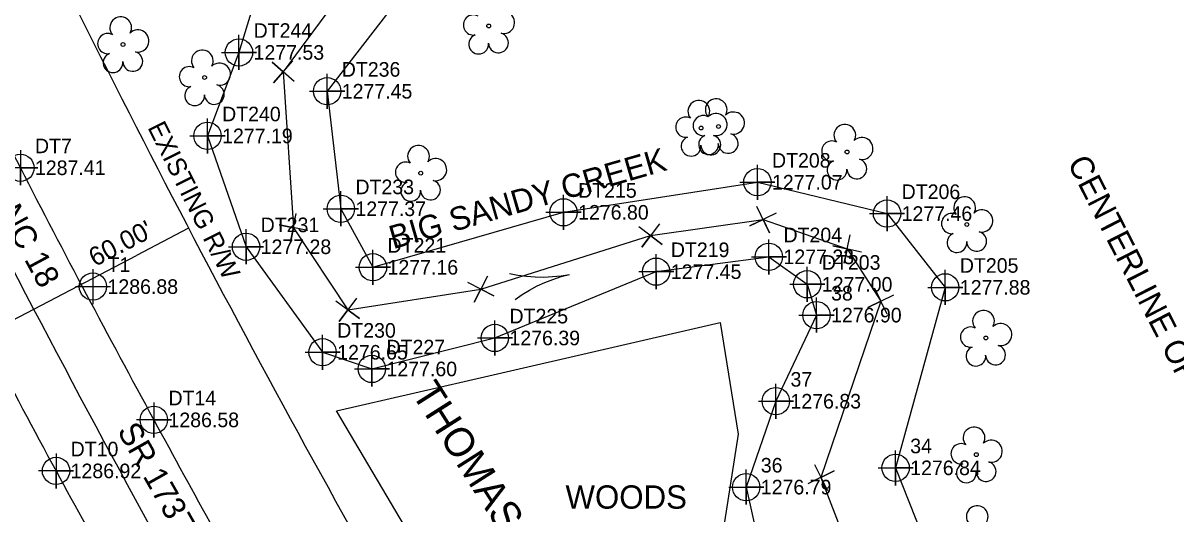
# Model space of a CAD drawing. Extents: x 1393723 to 1394549, y 957573 to 958412.
# Drawn here: x 1394117.7 to 1394315.1, y 958218.3 to 958302.5 of the extents above; entities that cross this region are included whole.
import ezdxf

# ---------------------------------------------------------------- set-up
doc = ezdxf.new("R2010")
doc.units = 0
for name, color, linetype in [('Cogo Default Point CELL', 7, 'Continuous'), ('COGO Default Point Elevation', 7, 'Continuous'), ('COGO Default Point Number', 7, 'Continuous'), ('Exist Horizontal Alignment', 7, 'Continuous'), ('Exist Hydro Jurisdictional Stream or Body of Water', 7, 'Continuous'), ('Exist Hydro Jurisdictional Stream or Body of Water Text', 7, 'Continuous'), ('Exist Hydro Stream Flow Arrow CELL', 7, 'Continuous'), ('Exist Hydro Stream or Body of Water Cogo Elevation', 7, 'Continuous'), ('Exist Hydro Stream or Body of Water Cogo Number', 7, 'Continuous'), ('Exist Hydro Stream or Body of Water Cogo Point CELL', 7, 'Continuous'), ('Exist Property Corner CELL', 7, 'Continuous'), ('Exist Property Line', 7, 'Continuous'), ('Exist Property Line Text', 7, 'Continuous'), ('Exist Property Owner Text', 7, 'Continuous'), ('Exist Right of Way Line', 7, 'Continuous'), ('Exist Right of Way Line Text', 7, 'Continuous'), ('Exist Right of Way Width CELL', 7, 'Continuous'), ('Exist Roads EOP', 7, 'Continuous'), ('Exist Roads EOP Cogo Elevation', 7, 'Continuous'), ('Exist Roads EOP Cogo Number', 7, 'Continuous'), ('Exist Roads EOP Cogo Point CELL', 7, 'Continuous'), ('Exist Roads EOP Text', 7, 'Continuous'), ('Exist Vegetation Tree CELL', 7, 'Continuous'), ('Exist Vegetation Woods Line', 7, 'Continuous'), ('Exist Vegetation Woods Line Text', 7, 'Continuous')]:
    doc.layers.add(name, color=color, linetype=linetype)

msp = doc.modelspace()

# ---------------------------------------------------------------- linework, layer by layer
at = {"layer": 'Cogo Default Point CELL'}
for points in [[(1394129.65, 958260.32), (1394129.65, 958257.32)], [(1394126.65, 958257.32), (1394129.65, 958257.32)], [(1394129.65, 958257.32), (1394132.65, 958257.32)], [(1394129.65, 958257.32), (1394129.65, 958254.32)]]:
    msp.add_lwpolyline(points, dxfattribs=at)
msp.add_circle((1394129.65, 958257.32), 2.34, dxfattribs=at)
at = {"layer": 'Exist Horizontal Alignment'}
msp.add_arc((1396149.77, 959316.7), 2291.83, 206.42564, 210.98819, dxfattribs=at)
at = {"layer": 'Exist Hydro Jurisdictional Stream or Body of Water'}
for points in [[(1394173.56, 958323.84), (1394160.39, 958316.41), (1394154.66, 958297.46), (1394149.27, 958283.15), (1394155.87, 958264.15), (1394168.98, 958246.06), (1394177.42, 958243.2), (1394198.48, 958248.51), (1394226.11, 958259.88), (1394245.4, 958262.42), (1394251.97, 958257.71), (1394253.55, 958252.43), (1394246.6, 958237.67), (1394241.52, 958222.95), (1394245.4, 958205.43), (1394258.52, 958177.52), (1394261.1, 958155.62), (1394254.7, 958129.06), (1394238.9, 958116.03), (1394219.59, 958103.52)], [(1394182.65, 958307.54), (1394169.76, 958290.8), (1394172.1, 958270.66), (1394177.6, 958260.63), (1394210.23, 958270.05), (1394243.43, 958275.21), (1394265.63, 958269.83), (1394275.6, 958257.19), (1394267.1, 958226.25), (1394278.61, 958197.12), (1394277.84, 958154), (1394270.52, 958123.51), (1394228.57, 958088.78)]]:
    msp.add_lwpolyline(points, dxfattribs=at)
at = {"layer": 'Exist Hydro Stream Flow Arrow CELL'}
msp.add_line((1394206.36, 958258.37), (1394206.36, 958258.37), dxfattribs=at)
for points in [[(1394200.99, 958259.57), (1394202.43, 958259.26), (1394203.92, 958259.1), (1394205.39, 958258.97), (1394206.84, 958258.96), (1394208.32, 958259.03), (1394209.81, 958259.18), (1394211.25, 958259.41)], [(1394201.94, 958255.09), (1394203.13, 958255.96), (1394204.43, 958256.71), (1394205.72, 958257.43), (1394207.03, 958258.03), (1394208.42, 958258.56), (1394209.84, 958259.03), (1394211.25, 958259.41)]]:
    msp.add_lwpolyline(points, dxfattribs=at)
at = {"layer": 'Exist Hydro Stream or Body of Water Cogo Point CELL'}
for points in [[(1394151.66, 958297.46), (1394157.66, 958297.46), (1394154.66, 958297.46), (1394154.66, 958294.46), (1394154.66, 958300.46)], [(1394166.76, 958290.8), (1394172.76, 958290.8), (1394169.76, 958290.8), (1394169.76, 958287.8), (1394169.76, 958293.8)], [(1394146.27, 958283.15), (1394152.27, 958283.15), (1394149.27, 958283.15), (1394149.27, 958280.15), (1394149.27, 958286.15)], [(1394240.43, 958275.21), (1394246.43, 958275.21), (1394243.43, 958275.21), (1394243.43, 958272.21), (1394243.43, 958278.21)], [(1394169.1, 958270.66), (1394175.1, 958270.66), (1394172.1, 958270.66), (1394172.1, 958267.66), (1394172.1, 958273.66)], [(1394207.23, 958270.05), (1394213.23, 958270.05), (1394210.23, 958270.05), (1394210.23, 958267.05), (1394210.23, 958273.05)], [(1394262.63, 958269.83), (1394268.63, 958269.83), (1394265.63, 958269.83), (1394265.63, 958266.83), (1394265.63, 958272.83)], [(1394152.87, 958264.15), (1394158.87, 958264.15), (1394155.87, 958264.15), (1394155.87, 958261.15), (1394155.87, 958267.15)], [(1394242.4, 958262.42), (1394248.4, 958262.42), (1394245.4, 958262.42), (1394245.4, 958259.42), (1394245.4, 958265.42)], [(1394174.6, 958260.63), (1394180.6, 958260.63), (1394177.6, 958260.63), (1394177.6, 958257.63), (1394177.6, 958263.63)], [(1394223.11, 958259.88), (1394229.11, 958259.88), (1394226.11, 958259.88), (1394226.11, 958256.88), (1394226.11, 958262.88)], [(1394248.97, 958257.71), (1394254.97, 958257.71), (1394251.97, 958257.71), (1394251.97, 958254.71), (1394251.97, 958260.71)], [(1394272.6, 958257.19), (1394278.6, 958257.19), (1394275.6, 958257.19), (1394275.6, 958254.19), (1394275.6, 958260.19)], [(1394250.55, 958252.43), (1394256.55, 958252.43), (1394253.55, 958252.43), (1394253.55, 958249.43), (1394253.55, 958255.43)], [(1394195.48, 958248.51), (1394201.48, 958248.51), (1394198.48, 958248.51), (1394198.48, 958245.51), (1394198.48, 958251.51)], [(1394165.98, 958246.06), (1394171.98, 958246.06), (1394168.98, 958246.06), (1394168.98, 958243.06), (1394168.98, 958249.06)], [(1394174.42, 958243.2), (1394180.42, 958243.2), (1394177.42, 958243.2), (1394177.42, 958240.2), (1394177.42, 958246.2)], [(1394243.6, 958237.67), (1394249.6, 958237.67), (1394246.6, 958237.67), (1394246.6, 958234.67), (1394246.6, 958240.67)], [(1394264.1, 958226.25), (1394270.1, 958226.25), (1394267.1, 958226.25), (1394267.1, 958223.25), (1394267.1, 958229.25)], [(1394238.52, 958222.95), (1394244.52, 958222.95), (1394241.52, 958222.95), (1394241.52, 958219.95), (1394241.52, 958225.95)]]:
    msp.add_lwpolyline(points, dxfattribs=at)
for centre in [(1394154.66, 958297.46), (1394169.76, 958290.8), (1394149.27, 958283.15), (1394243.43, 958275.21), (1394172.1, 958270.66), (1394210.23, 958270.05), (1394265.63, 958269.83), (1394155.87, 958264.15), (1394177.6, 958260.63), (1394245.4, 958262.42), (1394226.11, 958259.88), (1394251.97, 958257.71), (1394275.6, 958257.19), (1394253.55, 958252.43), (1394198.48, 958248.51), (1394168.98, 958246.06), (1394177.42, 958243.2), (1394246.6, 958237.67), (1394267.1, 958226.25), (1394241.52, 958222.95)]:
    msp.add_circle(centre, 2.34, dxfattribs=at)
at = {"layer": 'Exist Property Corner CELL'}
for p, q in [((1394162.21, 958294.13), (1394162.21, 958294.13)), ((1394244.41, 958268.82), (1394244.41, 958268.82)), ((1394163.98, 958267.41), (1394163.98, 958267.41)), ((1394225.15, 958266.05), (1394225.15, 958266.05)), ((1394258.8, 958263.77), (1394258.8, 958263.77)), ((1394196.06, 958256.89), (1394196.06, 958256.89)), ((1394173.29, 958253.34), (1394173.29, 958253.34)), ((1394264.57, 958254.81), (1394264.57, 958254.81)), ((1394254.31, 958224.6), (1394254.31, 958224.6))]:
    msp.add_line(p, q, dxfattribs=at)
for points in [[(1394164.09, 958292.48), (1394160.33, 958295.77), (1394162.21, 958294.13), (1394160.56, 958292.24), (1394163.86, 958296.01)], [(1394246.67, 958269.9), (1394242.16, 958267.73), (1394244.41, 958268.82), (1394245.5, 958266.56), (1394243.33, 958271.07)], [(1394166.43, 958266.91), (1394161.54, 958267.91), (1394163.98, 958267.41), (1394163.49, 958264.96), (1394164.48, 958269.86)], [(1394226.65, 958268.05), (1394223.65, 958264.05), (1394225.15, 958266.05), (1394227.15, 958264.55), (1394223.15, 958267.55)], [(1394261.24, 958263.24), (1394256.35, 958264.3), (1394258.8, 958263.77), (1394258.27, 958261.33), (1394259.33, 958266.21)], [(1394197.22, 958259.1), (1394194.91, 958254.67), (1394196.06, 958256.89), (1394198.28, 958255.73), (1394193.85, 958258.04)], [(1394265.68, 958252.57), (1394263.47, 958257.05), (1394264.57, 958254.81), (1394262.33, 958253.71), (1394266.82, 958255.92)], [(1394174.76, 958255.36), (1394171.81, 958251.32), (1394173.29, 958253.34), (1394175.31, 958251.87), (1394171.27, 958254.82)], [(1394253.2, 958226.84), (1394255.41, 958222.36), (1394254.31, 958224.6), (1394256.55, 958225.71), (1394252.07, 958223.5)]]:
    msp.add_lwpolyline(points, dxfattribs=at)
at = {"layer": 'Exist Property Line'}
for p, q in [((1394178.1, 958315.69), (1394162.21, 958294.13)), ((1394162.21, 958294.13), (1394163.98, 958267.41)), ((1394225.15, 958266.05), (1394244.41, 958268.82)), ((1394244.41, 958268.82), (1394258.8, 958263.77)), ((1394163.98, 958267.41), (1394173.29, 958253.34)), ((1394196.06, 958256.89), (1394225.15, 958266.05)), ((1394258.8, 958263.77), (1394264.57, 958254.81)), ((1394173.29, 958253.34), (1394196.06, 958256.89)), ((1394264.57, 958254.81), (1394254.31, 958224.6)), ((1394254.31, 958224.6), (1394268.57, 958187.32))]:
    msp.add_line(p, q, dxfattribs=at)
at = {"layer": 'Exist Right of Way Line'}
for radius, start in [(2170, 206.44093), (2230, 206.44083)]:
    msp.add_arc((1396069.16, 959272.56), radius, start, 210.98819, dxfattribs=at)
at = {"layer": 'Exist Right of Way Width CELL'}
for p in [(1394146.04, 958267.33), (1394092.86, 958239.53)]:
    msp.add_line(p, (1394137.11, 958262.66), dxfattribs=at)
at = {"layer": 'Exist Roads EOP'}
for points in [[(1394096.21, 958320.22), (1394117.22, 958277.69), (1394140.09, 958234.47), (1394160.7, 958197.15), (1394182.74, 958159.12)], [(1394078.9, 958312.9), (1394101.02, 958268.7), (1394123.33, 958225.72), (1394144.25, 958188.59), (1394165.82, 958150.9)]]:
    msp.add_spline(points, degree=3, dxfattribs=at)
at = {"layer": 'Exist Roads EOP Cogo Point CELL'}
for points in [[(1394117.22, 958280.69), (1394117.22, 958274.69), (1394117.22, 958277.69), (1394120.22, 958277.69), (1394114.22, 958277.69)], [(1394140.09, 958237.47), (1394140.09, 958231.47), (1394140.09, 958234.47), (1394143.09, 958234.47), (1394137.09, 958234.47)], [(1394123.33, 958228.72), (1394123.33, 958222.72), (1394123.33, 958225.72), (1394126.33, 958225.72), (1394120.33, 958225.72)]]:
    msp.add_lwpolyline(points, dxfattribs=at)
for centre in [(1394117.22, 958277.69), (1394140.09, 958234.47), (1394123.33, 958225.72)]:
    msp.add_circle(centre, 2.34, dxfattribs=at)
at = {"layer": 'Exist Vegetation Tree CELL'}
for p, q in [((1394197.42, 958302), (1394197.42, 958302)), ((1394134.8, 958298.82), (1394134.8, 958298.82)), ((1394148.77, 958293.15), (1394148.77, 958293.15)), ((1394236.77, 958284.76), (1394236.77, 958284.76)), ((1394233.79, 958284.5), (1394233.79, 958284.5)), ((1394258.79, 958280.4), (1394258.79, 958280.4)), ((1394185.78, 958276.77), (1394185.78, 958276.77)), ((1394279.3, 958267.97), (1394279.3, 958267.97)), ((1394282.54, 958248.51), (1394282.54, 958248.51)), ((1394280.92, 958228.52), (1394280.92, 958228.52))]:
    msp.add_line(p, q, dxfattribs=at)
for centre in [(1394197.42, 958302), (1394134.8, 958298.82), (1394148.77, 958293.15), (1394233.79, 958284.5), (1394236.77, 958284.76), (1394258.79, 958280.4), (1394185.78, 958276.77), (1394279.3, 958267.97), (1394282.54, 958248.51), (1394280.92, 958228.52)]:
    msp.add_circle(centre, 0.326, dxfattribs=at)
for centre, radius, start, end in [((1394199.96, 958302.59), 1.9, 257.1011, 134.1999), ((1394134.41, 958301.69), 1.86, 330.1651, 219.7134), ((1394194.81, 958302.16), 1.73, 62.6636, 279.3457), ((1394132.19, 958298.97), 1.73, 62.6636, 279.3457), ((1394137.34, 958299.41), 1.9, 257.1011, 134.1999), ((1394195.71, 958298.88), 1.69, 111.5671, 6.231), ((1394199.09, 958299.1), 1.7, 181.2822, 74.56), ((1394133.09, 958295.7), 1.69, 111.5671, 6.231), ((1394136.47, 958295.92), 1.7, 181.2822, 74.56), ((1394148.38, 958296.02), 1.86, 330.1651, 219.7134), ((1394146.16, 958293.3), 1.73, 62.6636, 279.3457), ((1394151.32, 958293.74), 1.9, 257.1011, 134.1999), ((1394147.06, 958290.03), 1.69, 111.5671, 6.231), ((1394150.44, 958290.25), 1.7, 181.2822, 74.56), ((1394233.4, 958287.37), 1.86, 330.1651, 219.7134), ((1394236.38, 958287.63), 1.86, 330.1651, 219.7134), ((1394234.16, 958284.91), 1.73, 62.6636, 279.3457), ((1394236.34, 958285.09), 1.9, 257.1011, 134.1999), ((1394239.32, 958285.35), 1.9, 257.1011, 134.1999), ((1394231.18, 958284.65), 1.73, 62.6636, 279.3457), ((1394258.4, 958283.27), 1.86, 330.1651, 219.7134), ((1394232.08, 958281.38), 1.69, 111.5671, 6.231), ((1394235.06, 958281.64), 1.69, 111.5671, 6.231), ((1394235.46, 958281.6), 1.7, 181.2822, 74.56), ((1394238.44, 958281.86), 1.7, 181.2822, 74.56), ((1394261.33, 958280.99), 1.9, 257.1011, 134.1999), ((1394185.4, 958279.64), 1.86, 330.1651, 219.7134), ((1394256.18, 958280.55), 1.73, 62.6636, 279.3457), ((1394188.33, 958277.36), 1.9, 257.1011, 134.1999), ((1394257.08, 958277.28), 1.69, 111.5671, 6.231), ((1394260.46, 958277.5), 1.7, 181.2822, 74.56), ((1394183.18, 958276.92), 1.73, 62.6636, 279.3457), ((1394184.08, 958273.65), 1.69, 111.5671, 6.231), ((1394187.45, 958273.87), 1.7, 181.2822, 74.56), ((1394278.92, 958270.84), 1.86, 330.1651, 219.7134), ((1394276.69, 958268.12), 1.73, 62.6636, 279.3457), ((1394281.85, 958268.56), 1.9, 257.1011, 134.1999), ((1394277.6, 958264.85), 1.69, 111.5671, 6.231), ((1394280.97, 958265.07), 1.7, 181.2822, 74.56), ((1394282.15, 958251.39), 1.86, 330.1651, 219.7134), ((1394279.93, 958248.67), 1.73, 62.6636, 279.3457), ((1394285.09, 958249.1), 1.9, 257.1011, 134.1999), ((1394284.21, 958245.61), 1.7, 181.2822, 74.56), ((1394280.84, 958245.39), 1.69, 111.5671, 6.231), ((1394280.53, 958231.39), 1.86, 330.1651, 219.7134), ((1394278.31, 958228.67), 1.73, 62.6636, 279.3457), ((1394283.47, 958229.1), 1.9, 257.1011, 134.1999), ((1394279.22, 958225.39), 1.69, 111.5671, 6.231), ((1394282.59, 958225.62), 1.7, 181.2822, 74.56), ((1394281.07, 958217.88), 1.86, 330.1651, 219.7134)]:
    msp.add_arc(centre, radius, start, end, dxfattribs=at)
at = {"layer": 'Exist Vegetation Woods Line'}
msp.add_lwpolyline([(1394224.39, 958146.28), (1394171.35, 958236.02), (1394198.19, 958242.19), (1394237.06, 958251.15), (1394240.14, 958232), (1394236.44, 958208.22), (1394240.14, 958193.4), (1394256.49, 958166.53), (1394247.86, 958136.58), (1394236.13, 958127), (1394225.03, 958148)], dxfattribs=at)

# ---------------------------------------------------------------- texts
at = {"layer": 'COGO Default Point Elevation'}
msp.add_text('1286.88', height=2.5, dxfattribs=at).set_placement((1394132.15, 958256.07))
at = {"layer": 'COGO Default Point Number'}
msp.add_text('T1', height=2.5, dxfattribs=at).set_placement((1394132.15, 958259.82))
at = {"layer": 'Exist Hydro Jurisdictional Stream or Body of Water Text'}
msp.add_text('BIG SANDY CREEK', height=4, rotation=16.1147, dxfattribs=at).set_placement((1394181.06, 958263.71))
at = {"layer": 'Exist Hydro Stream or Body of Water Cogo Elevation'}
for s, p in [('1277.53', (1394157.16, 958296.21)), ('1277.45', (1394172.26, 958289.55)), ('1277.19', (1394151.77, 958281.9)), ('1277.07', (1394245.93, 958273.96)), ('1277.37', (1394174.6, 958269.41)), ('1276.80', (1394212.73, 958268.8)), ('1277.46', (1394268.13, 958268.58)), ('1277.28', (1394158.37, 958262.9)), ('1277.23', (1394247.9, 958261.17)), ('1277.16', (1394180.1, 958259.38)), ('1277.45', (1394228.61, 958258.63)), ('1277.00', (1394254.47, 958256.46)), ('1277.88', (1394278.1, 958255.94)), ('1276.90', (1394256.05, 958251.18)), ('1276.39', (1394200.98, 958247.26)), ('1276.65', (1394171.48, 958244.81)), ('1277.60', (1394179.92, 958241.95)), ('1276.83', (1394249.1, 958236.42)), ('1276.84', (1394269.6, 958225)), ('1276.79', (1394244.02, 958221.7))]:
    msp.add_text(s, height=2.5, dxfattribs=at).set_placement(p)
at = {"layer": 'Exist Hydro Stream or Body of Water Cogo Number'}
for s, p in [('DT244', (1394157.16, 958299.96)), ('DT236', (1394172.26, 958293.3)), ('DT240', (1394151.77, 958285.65)), ('DT208', (1394245.93, 958277.71)), ('DT233', (1394174.6, 958273.16)), ('DT215', (1394212.73, 958272.55)), ('DT206', (1394268.13, 958272.33)), ('DT231', (1394158.37, 958266.65)), ('DT204', (1394247.9, 958264.92)), ('DT221', (1394180.1, 958263.13)), ('DT219', (1394228.61, 958262.38)), ('DT203', (1394254.47, 958260.21)), ('DT205', (1394278.1, 958259.69)), ('38', (1394256.05, 958254.93)), ('DT225', (1394200.98, 958251.01)), ('DT230', (1394171.48, 958248.56)), ('DT227', (1394179.92, 958245.7)), ('37', (1394249.1, 958240.17)), ('34', (1394269.6, 958228.75)), ('36', (1394244.02, 958225.45))]:
    msp.add_text(s, height=2.5, dxfattribs=at).set_placement(p)
at = {"layer": 'Exist Property Line Text'}
msp.add_text('CENTERLINE OF CREEK = PROPERTY LINE', height=4, rotation=297.0845, dxfattribs=at).set_placement((1394296.44, 958278.54))
at = {"layer": 'Exist Property Owner Text'}
msp.add_text('THOMAS HARDIN JOINES', height=5, rotation=302.4612, dxfattribs=at).set_placement((1394184.11, 958239.03))
at = {"layer": 'Exist Right of Way Line Text'}
msp.add_text('EXISTING R/W', height=3.2, rotation=296.5052, dxfattribs=at).set_placement((1394138.95, 958284.61))
at = {"layer": 'Exist Right of Way Width CELL'}
msp.add_text("60.00'", height=3.2, rotation=27.5965, dxfattribs=at).set_placement((1394130, 958260.66))
at = {"layer": 'Exist Roads EOP Cogo Elevation'}
for s, p in [('1287.41', (1394119.72, 958276.44)), ('1286.58', (1394142.59, 958233.22)), ('1286.92', (1394125.83, 958224.47))]:
    msp.add_text(s, height=2.5, dxfattribs=at).set_placement(p)
at = {"layer": 'Exist Roads EOP Cogo Number'}
for s, p in [('DT7', (1394119.72, 958280.19)), ('DT14', (1394142.59, 958236.97)), ('DT10', (1394125.83, 958228.22))]:
    msp.add_text(s, height=2.5, dxfattribs=at).set_placement(p)
at = {"layer": 'Exist Roads EOP Text'}
for s, rotation, p in [('TO NC 18', 298.4435, (1394109.19, 958277.93)), ('SR 1737 LONGBOTTOM RD.', 299.4504, (1394133.73, 958232.61))]:
    msp.add_text(s, height=4, rotation=rotation, dxfattribs=at).set_placement(p)
at = {"layer": 'Exist Vegetation Woods Line Text'}
msp.add_text('WOODS', height=4, dxfattribs=at).set_placement((1394210.57, 958219.25))

doc.saveas('drawing.dxf')
